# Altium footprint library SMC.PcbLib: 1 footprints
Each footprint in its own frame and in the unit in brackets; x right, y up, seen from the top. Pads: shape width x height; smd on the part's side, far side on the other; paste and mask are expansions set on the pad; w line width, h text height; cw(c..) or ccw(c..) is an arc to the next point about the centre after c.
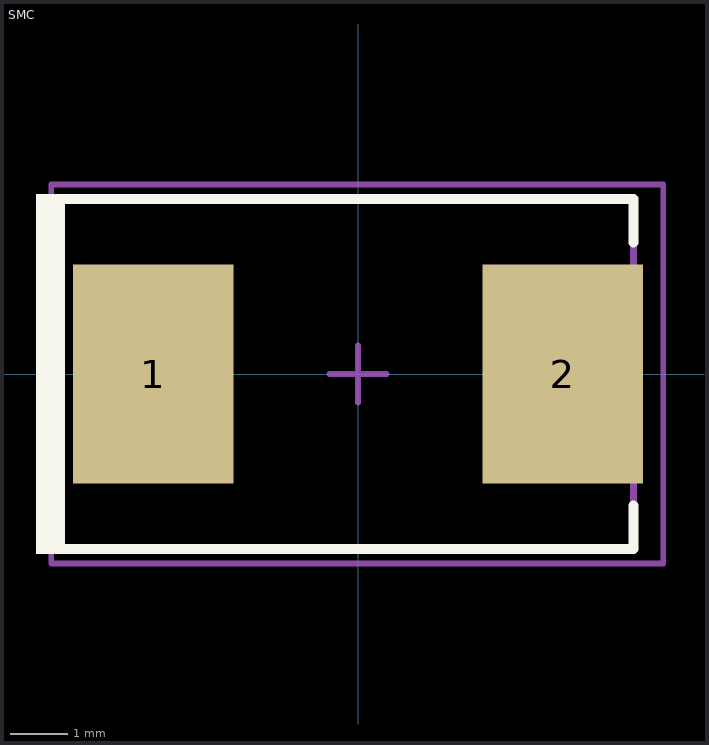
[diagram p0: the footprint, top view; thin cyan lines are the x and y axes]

## SMC [mil] "Molded Diode, 2-Leads, Body 6.9x5.8mm, IPC Medium Density, based on OnSemi component dimensions and land patterns"
height 94.88
pads (2):
  rect 110x150 smd: 1(-140.49,0) 2(140.49,0)
Top Overlay:
  rectangle: -221,-123.5 -201,123.5
  lines w7: -210,-120 189,-120 189,-90.25 ; -210,120 189,120 189,90.25
M5 Assembly Top:
  rectangle: -221,-123.5 -201,123.5
  lines w5: -210,-120 189,-120 189,120 -210,120
  text ".Designator" at -85,-20 h40
M15  Courtyards Top:
  lines w3.94: -19.69,0 19.68,0 ; 0,-19.68 0,19.68 ; -210.46,-129.92 -210.46,129.92 209.38,129.92 209.38,-129.92 -210.46,-129.92
3D body: height 91.35, standoff 0.6, extent -156.49,-116.13 156.5,116.15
